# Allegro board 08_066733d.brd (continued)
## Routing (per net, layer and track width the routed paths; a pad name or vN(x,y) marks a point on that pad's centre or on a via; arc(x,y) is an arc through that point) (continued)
PD_01/OSPI0_SELB/PPI0_D06: length 48
  TOP w0.203: U1.R3 v1(26.62,49.34)
  L8_SIG w0.127: v1(4.57,24.38) 5.01,24.82 5.96,24.82 7.49,26.35 7.49,27.69 8.97,29.16 12.39,29.16 13.36,28.19 v2(17.91,28.19)
  BOTTOM w0.14: J3.63 3.31,24.38 v1(4.57,24.38) ; v1(26.62,49.34) 26.22,48.94 26.22,44.79 24.89,43.46 24.89,40.98 24.04,40.13 22.16,40.13 20.89,38.86 20.89,36.7 19.05,34.86 19.05,32.89 21.34,30.61 21.34,28.57 20.95,28.19 v2(17.91,28.19)
PD_02/UART1_RTSB/SH1_FLG10/ETH0_CRS: length 58.5
  TOP w0.203: v1(27.42,50.14) U1.P4
  L4_SIG w0.127: v1(27.42,50.14) 27.02,50.54 27.02,51.14 26.82,51.34 22.82,51.34 22.02,50.54 22.02,46.66 20.38,45.02 20.38,42.29 20,41.91 20,40.85 20.51,40.34 20.51,35.9 19.47,34.85 19.47,28.92 21.88,26.51 21.88,18.47 22.99,17.37 22.99,8.38 26.04,5.33 v1(26.54,5.33)
  BOTTOM w0.14: v1(26.54,5.33) 26.72,5.51 J2.36
PD_03/UART1_CTSB/SH0_FLG11/LP0_ACK/ETH0_PTPAUXIN2: length 50.2
  TOP w0.203: v1(26.62,48.54) U1.T3
  L4_SIG w0.127: v1(26.62,48.54) 26.22,48.14 24.82,48.14 24.22,47.54 24.22,45.05 23.75,44.58 23.75,40.07 24.32,39.5 24.32,38.54 23.16,37.39 23.16,34.59 22.61,34.04 22.61,18.86 23.88,17.59 23.88,10.79 26.29,8.38 26.29,7.3 27.56,6.03 v1(27.56,5.33)
  BOTTOM w0.14: v1(27.56,5.33) 27.35,5.54 J2.38
PD_04/UART1_RXB/OSPI0_DQS/PPI0_D07/TM0_ACI1: length 89.2
  TOP w0.203: U1.V2 v1(25.82,46.94)
  L4_SIG w0.127: 3.62,23.05 7.68,23.05 9.33,24.7 9.33,26.77 9.35,26.79 9.35,29.98 10.92,31.56 v2(11.75,31.56)
  L4_SIG w0.14: v1(1.4,24.13) 2.54,24.13 3.62,23.05
  L5_SIG w0.127: v1(25.82,46.94) 25.42,46.54 24.74,46.54 23.34,45.14 16.56,45.14 14.48,43.05 14.48,41.02 13.73,40.28 13.73,37.14 13.63,37.04 13.63,33 12.83,32.19 12.38,32.19 v2(11.75,31.56)
  L7_SIG w0.127: v1(1.4,24.13) 0.95,23.69 0.95,21.72 2.29,20.38 2.29,11.87 5.08,9.08 10.01,9.08 11.93,7.16 21.86,7.16 22.86,6.16 23.18,6.16 23.75,5.59 23.75,4.95 v1(24.26,4.44)
  BOTTOM w0.14: v1(1.4,24.13) 1.9,23.62 J3.65 ; J2.27 24.26,3.16 v1(24.26,4.44) 25.32,4.44 26.08,5.21 J2.34
PD_05/UART1_TXB/PPI0_D08/ETH0_PTPAUXIN1: length 81.4
  TOP w0.203: v1(25.02,46.14) U1.W1
  L7_SIG w0.127: v1(25.02,46.14) 23.98,47.18 17.59,47.18 17.08,46.67 13.84,46.67 6.35,39.18 6.35,38.61 5.6,37.86 4.01,37.86 3.02,36.87 3.02,24.87 v1(1.4,23.24) 3.05,21.59 3.05,12.13 5.4,9.78 10.41,9.78 11.3,8.89 24.89,8.89 v1(25.65,8.13)
  BOTTOM w0.14: J3.67 1.65,22.99 v1(1.4,23.24) ; J2.32 25.45,7.92 v1(25.65,8.13)
PD_06/UART0_CTSB/ETH0_RX_ER: length 50.4
  TOP w0.203: v1(26.62,47.74) U1.U3
  L4_SIG w0.127: v1(31.24,4.44) 31.75,4.95 31.75,5.46 31.05,6.16 29.27,6.16 28.19,7.24 28.19,13.57 26.02,15.74 26.02,17.66 26.34,17.98 26.34,28.18 25.21,29.31 25.21,32.51 25.39,32.69 25.39,34.68 25.21,34.86 25.21,38.48 25.46,38.73 25.46,40.69 25.22,40.93 25.22,44.15 26.22,45.14 26.22,47.34 v1(26.62,47.74)
  BOTTOM w0.14: v1(31.24,4.44) 31.24,3.16 J2.49
PD_07/UART0_RTSB/ETH0_COL: length 54.9
  TOP w0.203: v1(27.42,48.54) U1.T4
  L4_SIG w0.127: v1(30.48,4.44) 30.99,3.94 31.79,3.94 32.86,5.01 32.86,6.12 32.5,6.49 29.45,6.49 28.57,7.37 28.57,13.65 26.35,15.88 26.35,17.53 26.67,17.84 26.67,28.32 25.72,29.27 25.72,30.23 26.23,30.73 26.23,32.89 25.72,33.4 25.72,35.62 26.1,36 26.1,37.72 25.83,37.99 25.83,40.06 26.48,40.7 26.48,44.42 27.02,44.96 27.02,48.14 27.16,48.28 v1(27.42,48.54)
  BOTTOM w0.14: J2.47 30.48,3.13 v1(30.48,4.44)
PD_08/UART0_RXB/TM0_ACI0: length 57.5
  TOP w0.203: v1(28.22,49.34) U1.R5
  L4_SIG w0.127: v1(30.35,1.65) 31.93,3.23 32.01,3.23 32.03,3.24 33.85,3.24 34.78,4.17 34.78,4.52 34.29,5.01 34.29,7.18 35.2,8.09 35.2,12.3 33.38,14.13 33.38,15.77 33.57,15.97 33.57,17.55 29.54,21.58 29.54,27.8 30.35,28.62 30.35,30.39 30.8,30.83 30.8,34.48 29.46,35.81 29.46,38.61 28.58,39.49 28.58,43.52 28.62,43.56 28.62,48.94 v1(28.22,49.34)
  BOTTOM w0.14: J2.45 29.89,2.11 v1(30.35,1.65)
PD_09/UART0_TXB: length 63.4
  TOP w0.203: v1(29.02,50.14) U1.P5
  L4_SIG w0.127: v1(29.02,50.14) 29.42,49.74 29.42,44.94 30.1,44.26 30.1,42.16 31.08,41.19 31.08,40.53 31.56,40.05 31.56,38.39 32.19,37.76 32.19,36.24 33.2,35.23 33.2,32.94 32.96,32.7 31.25,32.7 31.13,32.58 31.13,30.69 30.68,30.25 30.68,28.48 29.87,27.67 29.87,23.07 34.26,18.68 34.26,16.09 36.51,13.84 36.51,8.76 34.67,6.92 34.67,5.14 35.17,4.64 35.17,3.99 34.04,2.86 33.15,2.86 32.38,2.1 32.38,1.46 32.08,1.16 30.09,1.16 v1(29.59,1.65)
  BOTTOM w0.14: J2.43 29.26,1.98 v1(29.59,1.65)
PD_10/UART2_RXB/PPI0_D09/TM0_ACI2: length 91.4
  TOP w0.203: v1(28.22,50.14) U1.R4
  L7_SIG w0.127: v1(28.57,5.33) 27.37,6.54 22.99,6.54 22.03,7.49 12.07,7.49 10.15,9.41 5.26,9.41 2.67,12 2.67,21.21 v1(1.4,22.48)
  L8_SIG w0.127: v1(28.22,50.14) 27.82,50.54 24.12,50.54 23.51,49.93 18.46,49.93 15.45,46.93 10.54,46.93 10.03,46.42 10.03,41.97 9.56,41.49 6.09,38.02 6.08,38.02 4.9,36.84 4.33,36.84 2.03,34.54 2.03,23.11 v1(1.4,22.48)
  BOTTOM w0.14: J3.69 1.52,22.35 v1(1.4,22.48) ; v1(28.57,5.33) 28.62,5.38 J2.42
PD_11/UART2_TXB/PPI0_D10: length 82.1
  TOP w0.203: v1(26.62,46.14) U1.W3
  L7_SIG w0.127: v1(26.62,46.14) 26.22,45.74 24.62,45.74 23.56,46.8 17.68,46.8 17.22,46.34 13.98,46.34 11.75,44.11 11.75,42.54 11.18,41.97 9.61,41.97 6.73,39.09 6.73,38.29 5.32,36.88 4.08,36.88 3.35,36.16 3.35,23.72 4.46,22.62 v1(4.57,22.48) 3.94,21.84 3.94,15.43 8.39,10.97 24.84,10.97 v1(27.69,8.13)
  BOTTOM w0.14: v1(27.69,8.13) 27.99,7.75 J2.40 ; J3.71 4.32,21.72 4.57,21.97 v1(4.57,22.48)
PD_12/ETH0_PHY_INT/TM0_TMR6/UART2_RTSB/PPI0_D11: length 109.9
  TOP w0.203: v1(27.42,46.14) U1.W4
  L4_SIG w0.127: v1(1.52,42.42) 2.41,41.53 2.41,27.24 0.97,25.79 0.97,22.02 1.78,21.21 v1(4.57,21.21)
  L7_SIG w0.127: v1(27.42,46.14) 27.02,45.74 27.02,45.14 26.73,44.84 24.5,44.84 23.43,45.91 14.22,45.91 12.13,43.82 12.13,42.35 10.41,40.64 8.76,40.64 7.11,38.99 7.11,36.92 3.68,33.49 3.68,24.07 5.02,22.73 5.02,21.65 v1(4.57,21.21) 6.92,18.86 6.92,13.53 8.51,11.94 13.02,11.94 13.91,12.83 21.34,12.83 22.48,11.68 25.78,11.68 v1(29.34,8.13)
  BOTTOM w0.14: v1(4.57,21.21) 4.45,21.08 J3.73 ; v1(29.34,8.13) 29.26,7.75 J2.44 ; v1(1.52,42.42) 1.9,42.04 J3.7
PD_13/TM0_TMR7/UART2_CTSB/PPI0_D12: length 84.7
  TOP w0.203: v1(29.82,45.34) U1.Y7
  L7_SIG w0.127: v1(30.35,8.13) 29.72,7.49 29.21,7.49 25.4,11.3 8.68,11.3 6.48,13.5 6.48,18.29 v1(4.57,20.19)
  L8_SIG w0.127: v1(4.57,20.19) 4.06,20.7 4.06,33.27 4.95,34.16 6.79,34.16 8.51,35.88 11.28,35.88 12.26,36.85 12.26,39.62 14.8,42.16 17.57,42.16 17.57,42.16 17.84,42.16 19.88,42.16 20.45,42.74 29.32,42.74 29.82,43.24 v1(29.82,45.34)
  BOTTOM w0.14: v1(30.35,8.13) 29.89,7.62 J2.46 ; v1(4.57,20.19) 4.32,20.45 J3.75
PD_14/TWI4_SCL/LP1_ACK/SH1_FLG9/PPI0_D13: length 50.3
  TOP w0.203: v1(29.02,46.14) U1.W6
  L8_SIG w0.127: v1(29.02,46.14) 28.63,45.75 24.35,45.75 24.2,45.9 13.33,45.9 10.65,43.23 10.65,40.62 9.78,39.75 9.78,38.93 9.02,38.16 7.94,38.16 5.59,35.81 4.25,35.81 2.54,34.1 2.54,21.59 v1(1.4,20.45)
  BOTTOM w0.14: J3.77 2.03,19.81 v1(1.4,20.45)
PD_15/TWI4_SDA/MSI0_D0/TM0_TMR15/PPI0_D14: length 90.8
  TOP w0.14: U20.8 v1(31.67,34.29)
  L4_SIG w0.127: v1(33.07,1.97) 33.07,1.38 32.51,0.83 11.3,0.83 3.61,8.52 3.61,18.81 2.86,19.56 v1(1.4,19.56)
  L7_SIG w0.127: v1(33.07,1.97) 32.51,2.52 32.51,4.76 33.15,5.4 33.15,6.35 32.57,6.93 32.57,9.6 26.09,16.07 26.09,17.2 27.3,18.41 27.3,29.99 26.8,30.5 26.8,32.32 27.43,32.96 27.43,33.39 27.69,33.65 28.77,33.65 28.78,33.65 29.15,33.65 30.04,34.54 31.42,34.54 v1(31.67,34.29)
  BOTTOM w0.14: J3.79 1.78,19.18 v1(1.4,19.56) ; J2.55 v1(33.07,1.97)
PD_15/TWI4_SDA/MSI0_D0/TM0_TMR15/PPI0_D14_Z: length 22.2
  TOP w0.14: v1(32.62,34.34) 32.32,34.64 32.32,35.24 32.62,35.55 U20.9 ; U12.9 26.72,35.51 27.18,35.05 v1(27.62,35.05)
  TOP w0.203: v1(29.02,45.34) U1.Y6
  L4_SIG w0.127: v1(29.02,45.34) 29.02,44.07 29.53,43.56 29.53,41.34 31.11,39.75 31.11,35.85 v1(32.62,34.34)
  L8_SIG w0.127: v1(32.62,34.34) 31.59,35.37 29.59,35.37 29.08,35.88 28.59,35.88 28.58,35.87 28.44,35.87 v1(27.62,35.05)
PE_00/TWI5_SCL/SPI3_SEL3B/PPI0_D15: length 51.7
  TOP w0.203: v1(29.82,46.14) U1.W7
  L8_SIG w0.127: v1(29.82,46.14) 29.42,45.74 29.42,45.28 29.41,45.26 29.41,45.18 28.67,44.44 24.25,44.44 23.48,45.21 16.82,45.21 13.46,41.85 13.46,41.49 11.86,39.89 11.86,38.28 11.21,37.63 9.6,37.63 6.52,34.54 4.57,34.54 3.56,33.53 3.56,20.95 v1(1.4,18.8)
  BOTTOM w0.14: J3.81 1.65,18.54 v1(1.4,18.8)
PE_01/TWI5_SDA/MSI0_D1/SPI3_SEL4B/PPI0_FS1/TM0_ACLK15: length 81.8
  TOP w0.14: U20.11 33.02,36.83 33.36,36.49 33.82,36.49 v1(33.82,36.48)
  L7_SIG w0.127: v1(33.82,36.48) 33.59,36.25 33.59,33.19 34.02,32.75 34.02,32.27 33.9,32.14 32.65,32.14 31.88,31.37 31.37,31.37 29.72,29.72 28.96,29.72 27.81,28.57 27.81,18.35 28.68,17.49 28.68,14.06 32.9,9.84 32.9,8.76 33.53,8.13 33.53,5.27 32.96,4.7 32.96,3.17 33.7,2.43 v1(33.7,1.71)
  L8_SIG w0.127: v1(5.46,29.59) 5.96,30.09 5.96,32.43 8.19,34.67 15.33,34.67 16.09,33.91 20.68,33.91 21.52,34.75 22.34,34.75 22.59,35 22.59,35.01 24.54,36.96 26.23,36.96 27.31,38.04 28.7,38.04 28.84,37.89 31.83,37.89 32.38,37.34 32.97,37.34 v1(33.82,36.48)
  BOTTOM w0.14: J3.45 4.32,29.97 4.45,30.1 4.95,30.1 v1(5.46,29.59) ; J2.57 v1(33.7,1.71)
PE_01/TWI5_SDA/MSI0_D1/SPI3_SEL4B/PPI0_FS1/TM0_ACLK15_Z: length 22.3
  TOP w0.14: U20.12 33.02,37.33 33.34,37.65 33.34,38.74 v1(33.46,38.86) ; U12.12 27.42,37.33 v1(27.69,37.59)
  TOP w0.203: v1(31.42,47.74) U1.U9
  L4_SIG w0.127: v1(33.46,38.86) 33.46,40.58 31.78,42.26 31.78,44.65 31.83,44.69 31.83,47.33 v1(31.42,47.74)
  L7_SIG w0.127: v1(33.46,38.86) 32.32,40.01 29.78,40.01 29.41,39.64 29.41,37.67 28.86,37.11 28.16,37.11 v1(27.69,37.59)
PE_02/TWI0_SCL/SPI1_SEL4B/HADC0_MUX0/PPI0_FS2: length 40.5
  TOP w0.203: v1(30.62,46.94) U1.V8
  L7_SIG w0.127: v1(4.57,29.59) 4.57,32.04 5,32.48 5,33.45 10.48,38.93 11.87,38.93 13.84,40.89 13.84,42.1 16.89,45.15 23.26,45.15 24.22,44.18 28.69,44.18 29.43,44.94 29.43,47.26 29.53,47.35 30.21,47.35 v1(30.62,46.94)
  BOTTOM w0.14: J3.47 4.32,29.34 v1(4.57,29.59)
PE_03/TWI0_SDA/SPI2_SEL3B/HADC0_MUX2/PPI0_FS3/TM0_ACLK4: length 40.3
  TOP w0.203: v1(30.62,46.14) U1.W8
  L7_SIG w0.127: v1(4.57,28.83) 5.02,29.27 5.02,30.77 5.28,31.04 5.83,31.04 6.67,31.88 6.67,33.78 10.51,37.63 13.3,37.63 14.86,39.18 14.86,41.24 18.14,44.51 19.18,44.51 20.78,42.91 21.51,42.91 22.45,43.85 29.18,43.85 30.21,44.88 30.21,45.73 v1(30.62,46.14)
  BOTTOM w0.14: J3.49 4.45,28.7 v1(4.57,28.83)
PE_04/TWI2_SCL/HADC0_MUX1/PPI0_CLK: length 38.8
  TOP w0.203: v1(31.42,46.14) U1.W9
  L7_SIG w0.127: v1(31.42,46.14) 31.02,45.74 31.02,44.61 29.13,42.72 22.32,42.72 21.55,41.96 19.92,41.96 18.67,40.7 18.67,35.75 15.49,32.58 8.12,32.58 6.15,30.61 v1(5.46,30.61)
  BOTTOM w0.14: J3.43 5.46,30.61 v1(5.46,30.61)
PE_05/TWI2_SDA/PPI0_D00: length 48.7
  TOP w0.203: v1(32.22,46.94) U1.V10
  L7_SIG w0.127: v1(32.22,46.94) 31.83,47.33 31.83,47.9 31.6,48.13 28.77,48.13 28.63,48 28.63,45.2 27.94,44.51 24.36,44.51 23.35,45.53 16.76,45.53 13.4,42.16 13.4,41.08 12.51,40.2 10.35,40.2 8.64,38.48 8.13,38.48 7.44,37.8 7.44,36.78 4.01,33.35 4.01,28.37 4.19,28.19 4.83,28.19 v1(5.46,27.56)
  BOTTOM w0.14: J3.51 4.45,28.07 4.95,28.07 v1(5.46,27.56)
PE_06/TM0_TMR8/SH0_FLG2/MSI0_D2/PPI0_D01: length 67.7
  TOP w0.14: U22.3 28.64,32.07 v1(28.45,32.26)
  L4_SIG w0.127: v1(28.45,32.26) 28.7,32.01 28.7,30.86 28.19,30.35 27.51,30.35 27.3,30.15 27.3,29.34 28.17,28.47 28.17,19.08 29.78,17.46 29.78,15.94 29.4,15.56 29.4,9.4 29.84,8.95 29.84,7.68 30.38,7.15 33.43,7.15 33.96,6.62 33.96,4.87 34.34,4.5 v1(34.34,4.34)
  L8_SIG w0.127: v1(4.57,27.56) 5.21,28.19 5.78,28.19 6.29,28.7 6.29,32.3 8.33,34.34 15.19,34.34 16.07,33.46 19.99,33.46 21.2,32.26 23.05,32.26 23.63,32.83 27.84,32.83 27.89,32.78 27.92,32.78 v1(28.45,32.26)
  BOTTOM w0.14: J2.59 v1(34.34,4.34) ; J3.53 3.31,27.56 v1(4.57,27.56)
PE_06/TM0_TMR8/SH0_FLG2/MSI0_D2/PPI0_D01_Z: length 38.1
  TOP w0.14: U22.2 29.1,32.57 28.96,32.71 v1(28.96,33.22) ; v1(21.95,33.45) 22.62,33.45 23.32,32.75 U21.2
  TOP w0.203: v1(32.22,47.74) U1.U10
  L7_SIG w0.127: v1(21.95,33.45) 20.71,33.45 19.44,34.72 19.44,38.37 21.86,40.79 21.86,41.26 22.66,42.06 31.69,42.06 32.65,43.03 32.65,47.31 v1(32.22,47.74)
  L8_SIG w0.127: v1(21.95,33.45) 22.13,33.27 25.02,33.27 25.91,34.16 26.77,34.16 27.28,33.66 28.52,33.66 v1(28.96,33.22)
PE_07/TM0_TMR9/SH0_FLG3/SPI1_RDY/PPI0_D02: length 53.6
  TOP w0.203: v1(34.62,46.14) U1.W12
  L7_SIG w0.127: v1(4.57,26.54) 4.14,26.11 4.14,25.15 4.39,24.89 5.71,24.89 6.54,24.07 8.74,24.07 9.31,24.64 21.82,24.64 25.67,28.49 25.67,29.69 24.82,30.54 24.82,32.97 26.16,34.31 27.85,34.31 28.47,34.92 28.86,34.92 29.3,35.37 31.88,35.37 33.42,36.92 34.25,36.92 34.59,37.26 34.59,38.58 33.97,39.2 33.97,40.26 34.86,41.15 34.86,44.51 35.03,44.68 35.03,45.73 v1(34.62,46.14)
  BOTTOM w0.14: v1(4.57,26.54) 4.32,26.8 J3.55
PE_08/TM0_TMR0/MSI0_D3/PPI0_D03: length 68.3
  TOP w0.14: U22.6 v1(29.22,29.29)
  L7_SIG w0.127: v1(29.22,29.29) 28.38,28.45 28.38,18.54 29.84,17.08 29.84,13.36 33.23,9.97 33.23,8.89 33.86,8.26 33.86,3.15 v1(34.97,2.03)
  L8_SIG w0.127: v1(5.14,25.91) 5.97,25.91 6.68,26.62 6.68,32.08 7.37,32.77 11.43,32.77 11.57,32.63 17.67,32.63 19.11,31.18 20.88,31.18 21.34,30.72 21.34,29.34 22.8,27.88 27.82,27.88 v1(29.22,29.29)
  BOTTOM w0.14: J2.61 v1(34.97,2.03) ; v1(5.14,25.91) 5.08,25.97 4.51,25.97 4.32,26.16 J3.57
PE_08/TM0_TMR0/MSI0_D3/PPI0_D03_Z: length 41.8
  TOP w0.14: U21.5 22.35,31.07 v1(22.1,30.81) ; U22.5 28.84,31.07 28.77,30.99 28.76,30.99 28.51,30.74 v1(28.51,29.92)
  TOP w0.203: v1(31.42,46.94) U1.V9
  L7_SIG w0.127: v1(31.42,46.94) 31.81,46.55 31.81,43.56 30.65,42.39 22.45,42.39 21.69,41.63 20.1,41.63 19.05,40.58 19.05,32.89 21.13,30.81 v1(22.1,30.81)
  L8_SIG w0.127: v1(22.1,30.81) 21.72,30.44 21.72,29.71 22.16,29.28 23.23,29.28 23.24,29.27 23.24,29.27 24,30.03 26.93,30.03 27.68,29.28 27.86,29.28 v1(28.51,29.92)
PE_09/TM0_TMR1/MSI0_CLK/PPI0_D04/ETH0_PTPAUXIN3: length 93.1
  TOP w0.14: v1(37.41,28.99) 37.58,29.16 U25.8
  L5_SIG w0.127: v1(37.41,28.99) 37.45,28.96 37.45,18.3 38.54,17.21 38.54,8 40.26,6.29 44.96,6.29 45.72,5.52 45.72,4.64 44.64,3.56 35.62,3.56 34.77,4.41 34.77,6.24 v1(33.07,7.94)
  L8_SIG w0.127: v1(37.41,28.99) 36.47,28.99 35.16,27.69 28.64,27.69 28.07,27.11 21.46,27.11 19.34,29.24 19.34,29.94 18.1,31.18 16.64,31.18 16.19,30.73 11.81,30.73 10.16,32.38 7.49,32.38 7.01,31.9 7.01,26.38 5.78,25.15 4.95,25.15 v1(4.57,25.53)
  BOTTOM w0.14: J2.56 v1(33.07,7.94) ; v1(4.57,25.53) 3.18,25.53 J3.59
PE_09/TM0_TMR1/MSI0_CLK/PPI0_D04/ETH0_PTPAUXIN3_Z: length 24.5
  TOP w0.14: U23.9 38.72,35.83 v1(39.43,35.12) ; U25.9 v1(38.53,29.73)
  TOP w0.203: v1(32.22,46.14) U1.W10
  L4_SIG w0.127: v1(39.43,35.12) 38.93,35.12 38.54,35.5 35.94,35.5 35.43,36 35.43,37.38 33.97,38.84 33.97,40.32 34.29,40.64 34.29,41.47 32.69,43.07 32.69,45.67 v1(32.22,46.14)
  BOTTOM w0.14: v1(38.53,29.73) 38.53,33.77 39.43,34.67 v1(39.43,35.12)
PE_10/TM0_TMR2/SPI0_SEL4B/PPI0_D05: length 77
  TOP w0.14: v1(42.02,44.14) 40.52,44.14 39.92,44.74 22.99,44.74 22.45,45.28 18.92,45.28 17.06,43.41 14.64,43.41 14.29,43.05 14.29,40.2 14.83,39.66 14.83,39.21 14.51,38.89 14.51,38.89 12.19,36.58 12.19,35.37 10.79,33.97 10.79,31.18 11.53,30.45 11.53,30.45 11.65,30.32 11.65,26.11 11.44,25.9 9.9,25.9 9.27,25.27 9.27,24.89 7.38,23 3.56,23 v1(1.42,25.14)
  TOP w0.203: v1(41.02,57.34) U1.F20
  BOTTOM w0.14: v1(41.02,57.34) 41.42,56.94 41.42,45.74 42.02,45.14 v1(42.02,44.14) ; v1(1.42,25.14) 1.67,24.89 J3.61
PE_11/ETH1_REFCLK/SH1_FLG7: length 79
  TOP w0.203: v1(40.22,56.54) U1.G19
  L8_SIG w0.127: v1(4.57,19.3) 5.78,19.3 7.68,21.21 17.72,21.21 20.05,18.87 26.05,18.87 27.75,20.57 35.7,20.57 35.83,20.7 35.83,25.66 36.19,26.02 36.84,26.02 37.65,26.02 38.61,26.98 38.61,27.56 38.96,27.9 41.88,27.9 v1(42.1,27.69)
  BOTTOM w0.14: v1(4.57,19.3) 5.08,19.81 J3.78 ; v1(40.22,56.54) 40.46,56.3 40.62,56.14 40.62,44.98 41.44,44.16 41.44,28.35 v1(42.1,27.69)
PE_12/ETH1_TXEN/SH0_FLG8: length 46.1
  TOP w0.203: v1(39.42,55.74) U1.H18
  L7_SIG w0.127: v1(39.42,55.74) U1.H18 24.32,55.34 23.62,54.64 21.59,54.64 21.56,54.61 20.24,54.61 17.77,52.18 9.94,52.18 8.16,50.41 8.16,43.98 v1(5.33,41.15)
  BOTTOM w0.14: v1(5.33,41.15) 5.71,40.77 J3.12
PE_13/ETH1_TXD0/SH1_FLG13: length 45.2
  TOP w0.203: v1(38.62,54.94) U1.J17
  L7_SIG w0.127: v1(5.33,40.39) 8.51,43.56 8.51,50.04 10.27,51.8 18.37,51.8 20.13,53.54 23.42,53.54 24.42,54.54 U1.J17 v1(38.62,54.94)
  BOTTOM w0.14: J3.14 5.59,40.13 v1(5.33,40.39)
PE_14/ETH1_TXD1/SPI2_SEL7B: length 46.6
  TOP w0.203: v1(37.82,53.34) U1.K16
  L7_SIG w0.127: v1(4.57,39.12) 4.57,39.5 4.7,39.62 5.27,39.62 9.59,43.94 9.59,50.48 10.53,51.42 18.91,51.42 20.03,52.54 23.42,52.54 24.62,53.74 U1.K16 v1(37.82,53.34)
  BOTTOM w0.14: J3.16 6.65,39.62 5.08,39.62 v1(4.57,39.12)
PE_15/ETH1_RXD0/SPI0_SEL6B: length 45.2
  TOP w0.203: v1(39.42,56.54) U1.G18
  L7_SIG w0.127: v1(39.42,56.54) U1.G18 22.62,56.14 21.42,54.94 19.52,54.94 17.05,52.51 9.09,52.51 v1(8.82,52.24)
  BOTTOM w0.14: v1(8.82,52.24) 8.82,46.41 8,45.59 8,41.66 7.75,41.4 J3.10
PF_00/ETH1_RXD1/SPI3_RDY/SPI0_SEL7B: length 47.8
  TOP w0.203: v1(40.22,57.34) U1.F19
  L7_SIG w0.127: v1(40.22,57.34) U1.F19 25.42,56.94 25.34,57.02 21.91,57.02 20.92,56.04 19.82,56.04 16.71,52.93 8.59,52.93 7.75,52.09 7.75,44.45 v1(5.33,42.04)
  BOTTOM w0.14: J3.8 6.78,42.04 v1(5.33,42.04)
PF_01/ETH1_MDIO/SH0_FLG7: length 46.7
  TOP w0.203: v1(39.42,57.34) U1.F18
  L7_SIG w0.127: v1(5.33,43.31) 6.03,43.31 7.37,44.64 7.37,52.2 8.47,53.3 14.82,53.3 16.07,54.55 17.63,54.55 20.55,57.47 25.45,57.47 25.72,57.74 39.02,57.74 v1(39.42,57.34)
  BOTTOM w0.14: v1(5.33,43.31) 6.78,43.31 J3.4
PF_02/ETH1_MDC/SH0_FLG6: length 52.3
  TOP w0.203: v1(41.02,58.14) U1.E20
  L7_SIG w0.127: v1(41.02,58.14) 40.62,58.54 25.84,58.54 25.39,58.99 18.77,58.99 17.12,57.34 17.12,55.84 16.62,55.34 7.84,55.34 6.22,53.72 6.22,48.39 4.57,46.74 v1(4.57,43.31)
  BOTTOM w0.14: J3.6 5.21,42.67 v1(4.57,43.31)
PF_03/ETH1_CRS/SH0_FLG10/USB0_STP: length 89.1
  TOP w0.203: v1(40.22,58.14) U1.E19
  L4_SIG w0.127: v1(58.8,35.56) 55.37,38.99 55.37,41.91 54.18,43.1 54.18,52.14 54.1,52.22 54.1,52.26 48.62,57.74 40.62,57.74 v1(40.22,58.14)
  L7_SIG w0.127: v1(40.22,58.14) 40.62,57.74 40.62,53.84 39.72,52.94 24.62,52.94 23.82,52.14 22.02,52.14 20.82,51.04 10.78,51.04 10.03,50.29 10.03,43.81 v1(5.33,39.12)
  BOTTOM w0.14: v1(5.33,39.12) 5.59,38.86 J3.18 ; J1.76 58.04,36.32 v1(58.8,35.56)
PF_04/USB0_D7/TM0_ACLK13: length 34.8
  TOP w0.203: v1(38.62,55.74) U1.H17
  L5_SIG w0.127: v1(54.23,35.43) 52.32,37.34 52.32,44.74 50.93,46.13 50.93,51.37 46.74,55.56 42.8,55.56 42.58,55.34 39.02,55.34 v1(38.62,55.74)
  BOTTOM w0.14: J1.72 54.61,35.05 v1(54.23,35.43)
PF_05/MLB0_CLKOUT/USB0_D6/TM0_CLK: length 36.3
  TOP w0.203: v1(37.02,54.94) U1.J16
  L5_SIG w0.127: v1(54.23,34.67) 51.99,36.91 51.99,44.53 50.55,45.97 50.55,51.28 47.29,54.54 U1.J16 v1(37.02,54.94)
  BOTTOM w0.14: v1(54.23,34.67) 54.48,34.42 J1.70
PF_06/SH1_FLG2/SPI1_SEL7B/USB0_D5: length 38.1
  TOP w0.203: v1(38.62,56.54) U1.G17
  L5_SIG w0.127: v1(55.25,33.91) 55.75,34.42 55.75,42.16 54.36,43.56 54.36,50.61 49.33,55.64 47.72,55.64 46.36,57 42.33,57 42.27,56.94 39.02,56.94 v1(38.62,56.54)
  BOTTOM w0.14: J1.68 55.37,33.78 v1(55.25,33.91)
PF_07/SH1_FLG3/SPI3_SEL2B/USB0_D4: length 40.7
  TOP w0.203: v1(41.02,58.94) U1.D20
  L5_SIG w0.127: v1(58.8,34.29) 58.17,34.92 57.53,34.92 57.09,35.37 57.09,43.05 56.13,44.01 56.13,51.75 49.34,58.55 47.31,58.55 46.61,59.25 45.15,59.25 44.96,59.44 43.12,59.44 42.62,58.94 v1(41.02,58.94)
  BOTTOM w0.14: J1.66 57.91,33.15 58.17,33.4 58.17,33.65 v1(58.8,34.29)
PF_08/SPI3_SEL6B/SH1_FLG8/USB0_NXT/TM0_TMR11: length 40.8
  TOP w0.203: v1(40.22,58.94) U1.D19
  L5_SIG w0.127: v1(58.04,35.56) 57.53,36.07 57.53,43.31 56.52,44.32 56.52,54.42 52.26,58.67 50.48,58.67 48.83,60.33 42.54,60.33 41.55,59.33 40.61,59.33 v1(40.22,58.94)
  BOTTOM w0.14: J1.74 57.91,35.69 v1(58.04,35.56)
PF_09/SH0_FLG9/USB0_DIR: length 36.8
  TOP w0.203: v1(41.02,59.74) U1.C20
  L4_SIG w0.127: v1(58.42,37.08) 55.75,39.75 55.75,52.77 49.58,58.94 44.82,58.94 44.02,59.74 v1(41.02,59.74)
  BOTTOM w0.14: v1(58.42,37.08) 56.81,37.08 J1.78
PF_10/SH1_FLG4/USB0_D3: length 41.8
  TOP w0.203: v1(39.42,58.14) U1.E18
  L5_SIG w0.127: v1(39.42,58.14) 39.82,58.54 41.52,58.54 42.4,57.66 48.7,57.66 55.75,50.61 55.75,43.75 56.64,42.86 56.64,34.73 58.1,33.27 v1(58.8,33.27)
  BOTTOM w0.14: v1(58.8,33.27) 58.04,32.51 J1.64
PF_11/SH1_FLG5/USB0_D2: length 41
  TOP w0.203: v1(38.62,57.34) U1.F17
  L5_SIG w0.127: v1(55.25,32.26) 56.2,33.21 56.2,42.74 55.37,43.56 55.37,50.36 49.69,56.04 48.02,56.04 46.73,57.33 42.26,57.33 41.85,57.74 39.02,57.74 v1(38.62,57.34)
  BOTTOM w0.14: v1(55.25,32.26) 55.63,31.88 J1.62
PF_12/SH0_FLG13/USB0_D1: length 40.9
  TOP w0.203: v1(37.82,55.74) U1.H16
  L5_SIG w0.127: v1(55.25,31.5) 54.76,31.98 54.76,35.88 53.53,37.11 53.53,38.91 54.36,39.74 54.36,42.87 53.72,43.51 53.72,50.67 49.91,54.48 48.32,54.48 46.88,55.93 41.68,55.93 41.47,56.14 38.22,56.14 v1(37.82,55.74)
  BOTTOM w0.14: J1.60 55.5,31.24 v1(55.25,31.5)
PF_13/SH0_FLG12/USB0_D0: length 46.8
  TOP w0.203: v1(41.02,60.54) U1.B20
  L4_SIG w0.127: v1(58.04,31.5) 59.44,32.89 59.44,40.39 59.06,40.77 58.04,40.77 56.52,42.29 56.52,55.75 51.73,60.54 v1(41.02,60.54)
  BOTTOM w0.14: v1(58.04,31.5) 58.04,30.86 57.79,30.61 J1.58
PF_14/SH1_FLG12/USB0_CLK: length 38.8
  TOP w0.203: v1(40.22,59.74) U1.C19
  L4_SIG w0.127: v1(40.22,59.74) 40.62,60.14 49.4,60.14 50.93,58.61 52.7,58.61 56.13,55.17 56.13,40.13 v1(58.42,37.85)
  BOTTOM w0.14: J1.80 58.17,37.59 v1(58.42,37.85)
PF_15/CAN0_RX/TM0_ACI4: length 53.3
  TOP w0.203: v1(32.22,48.54) U1.T10
  L4_SIG w0.127: v1(36.32,5.33) 38.58,7.59 38.58,18.42 35.69,21.32 35.69,28.07 40.21,32.59 40.21,36.6 37.21,39.6 37.21,40.58 34.23,43.56 34.23,47.88 33.96,48.15 32.61,48.15 v1(32.22,48.54)
  BOTTOM w0.14: v1(36.32,5.33) 36.32,6.61 J2.66
PG1: length 34.9
  TOP w0.254: v2(21.08,12.06) 21.27,12.26 R100.1 20.06,12.77 19.87,12.96 19.87,13.26 19.86,13.26 19.86,13.76 19.63,13.99 VR1.1 ; U17.2 46.46,14.67 46.73,14.4 46.81,14.4 v2(47.12,14.1)
  L8_SIG w0.305: v2(21.08,12.06) 28.7,12.06 29.91,13.27 32.39,13.27 34.99,10.67 42.8,10.67 43.94,11.81 46.36,11.81 47.12,12.57 v2(47.12,14.1)
PG2: length 12.9
  TOP w0.254: v2(43.56,13.46) 44.58,13.46 44.84,13.72 U17.11
  TOP w0.305: v2(43.56,13.46) 43.18,13.08 R104.1
  L8_SIG w0.305: v2(43.56,13.46) 42.43,14.6 v2(34.92,14.6)
  BOTTOM w0.254: R92.1 v2(34.92,14.6)
PG_00/CAN0_TX/TM0_ACLK10: length 48.5
  TOP w0.203: v1(33.82,47.74) U1.U11
  L5_SIG w0.127: v1(39.37,8.13) 38.87,8.62 38.87,20.62 38.04,21.46 38.04,29.72 35.43,32.32 35.14,32.32 34.7,32.76 34.7,33.5 33.53,34.67 33.53,36.17 33.39,36.31 33.39,36.66 33.39,37.96 33.97,38.54 33.97,38.99 33.38,39.58 33.38,47.3 v1(33.82,47.74)
  BOTTOM w0.14: v1(39.37,8.13) 35.99,8.13 35.61,7.75 J2.64
PG_01/CAN1_RX/SPI2_SEL6B/MSI0_CMD/TM0_ACI11: length 45.3
  TOP w0.14: v1(28.32,37.59) 28.59,37.33 U20.3
  L4_SIG w0.127: v1(33.7,9.35) 33.7,11.95 33.05,12.61 33.05,15.91 33.24,16.11 33.24,17.41 29.21,21.45 29.21,27.94 30.02,28.75 30.02,30.3 29.79,30.53 29.79,32.72 30.47,33.39 30.47,34.24 29.13,35.57 29.13,36.78 v1(28.32,37.59)
  L5_SIG w0.127: v1(33.7,9.35) 37.66,5.39 37.66,4.76 37.97,4.44 v1(38.61,4.44)
  BOTTOM w0.14: J2.72 38.15,4.91 v1(38.61,4.44) ; J2.58 v1(33.7,9.35)
PG_01/CAN1_RX/SPI2_SEL6B/MSI0_CMD/TM0_ACI11_Z: length 21.9
  TOP w0.14: U20.2 29.1,37.83 28.96,37.97 v1(28.96,38.48) ; U12.2 23.19,37.83 v1(22.29,38.73)
  TOP w0.203: v1(33.82,46.14) U1.W11
  L7_SIG w0.127: v1(33.82,46.14) 34.21,45.75 34.21,44.91 34.48,44.64 34.48,42.44 32.43,40.39 29.53,40.39 28.96,39.81 v1(28.96,38.48) 28.52,38.04 22.98,38.04 v1(22.29,38.73)
PG_02/CAN1_TX/SPI0_SEL5B/MSI0_D4: length 37.3
  TOP w0.14: U22.8 v1(31.67,29.03)
  L4_SIG w0.127: v1(35.61,1.71) 35.61,2.97 v1(37.08,4.44)
  L7_SIG w0.127: v1(31.67,29.03) 31.35,28.7 31.24,28.7 29.59,27.05 29.59,20.89 33.27,17.21 33.27,15.13 33.05,14.9 33.05,13.75 33.82,12.98 33.82,10.82 37.64,7 37.64,5 v1(37.08,4.44)
  BOTTOM w0.14: J2.70 37.59,6.61 37.59,4.95 v1(37.08,4.44) ; J2.63 v1(35.61,1.71)
PG_02/CAN1_TX/SPI0_SEL5B/MSI0_D4_Z: length 34.3
  TOP w0.14: v1(32.62,29.46) U22.9 ; U21.9 27.04,30.57 v1(27.75,29.86)
  TOP w0.203: v1(33.82,46.94) U1.V11
  L4_SIG w0.127: v1(33.82,46.94) 33.39,46.51 33.39,42.94 35.81,40.51 36.45,40.51 36.77,40.2 36.77,39.12 38.23,37.66 38.23,36.64 39.29,35.57 39.67,35.57 39.88,35.37 39.88,34.8 38.35,33.27 38.35,32.45 35.05,29.15 32.94,29.15 v1(32.62,29.46)
  L8_SIG w0.127: v1(27.75,29.86) 28.25,30.35 31.74,30.35 v1(32.62,29.46)
PG_03/UART3_TXB: length 67
  TOP w0.203: v1(36.22,45.34) U1.Y14
  L4_SIG w0.127: v1(36.22,45.34) 36.22,44.87 38.1,42.99 38.1,42.12 39.51,40.71 39.51,39.8 41.2,38.11 41.2,30.53 37.02,26.35 37.02,25.59 v1(37.02,25.59)
  L8_SIG w0.127: v1(37.02,25.59) 37.47,25.15 37.47,21.08 36.58,20.19 31.18,20.19 29.53,18.54 19.92,18.54 17.63,20.83 8,20.83 5.84,18.67 v1(4.57,18.67)
  BOTTOM w0.14: v1(4.57,18.67) 5.08,19.18 J3.80
PG_04/UART3_RXB/TM0_ACI13: length 72.8
  TOP w0.203: v1(35.42,46.94) U1.V13
  L4_SIG w0.127: v1(39.59,20.57) 36.17,23.99 36.17,26.52 40.54,30.89 40.54,36.74 38.99,38.29 38.99,39.18 38.3,39.87 38.3,40.12 35.02,43.4 35.02,46.54 v1(35.42,46.94)
  L8_SIG w0.127: v1(4.57,18.03) 6.48,18.03 8.13,19.68 9.48,19.68 11.01,18.16 29.65,18.16 30.42,18.92 36.07,18.92 38.23,21.08 39.08,21.08 v1(39.59,20.57)
  BOTTOM w0.14: v1(4.57,18.03) 5.08,18.54 J3.82
PG_05/SPI3_CLK/TM0_ACLK11: length 38
  TOP w0.203: v1(36.22,46.14) U1.W14
  L7_SIG w0.127: v1(61.09,45.72) 61.09,37.34 v1(61.72,36.7)
  L8_SIG w0.127: v1(61.09,45.72) 59.56,45.72 58.93,46.36 54.58,46.36 53.11,44.89 41.06,44.89 41,44.83 38.43,44.83 38.22,45.04 38.22,45.54 38.02,45.74 36.62,45.74 v1(36.22,46.14)
  BOTTOM w0.14: J1.77 61.47,36.96 v1(61.72,36.7)
PG_06/SPI3_MISO: length 41.4
  TOP w0.203: v1(33.82,48.54) U1.T11
  L5_SIG w0.127: v1(61.72,37.46) 60.58,38.61 60.58,48.89 v1(59.94,49.53)
  L8_SIG w0.127: v1(59.94,49.53) 48.64,49.53 48.04,48.93 34.21,48.93 v1(33.82,48.54)
  BOTTOM w0.14: v1(61.72,37.46) 61.59,37.59 J1.79
PG_07/SPI3_MOSI/TM0_ACLK12: length 39.3
  TOP w0.203: v1(34.62,47.74) U1.U12
  L5_SIG w0.127: v1(58.42,38.61) 59.44,39.62 59.44,48.01 v1(59.94,48.51)
  L8_SIG w0.127: v1(34.62,47.74) 35.01,48.13 48.42,48.13 48.48,48.07 49.59,48.07 50.67,49.15 59.31,49.15 v1(59.94,48.51)
  BOTTOM w0.14: J1.81 58.8,38.23 v1(58.42,38.61)
PG_08/SPI3_SEL1B/MSI0_D5/SPI3_SSB: length 96.8
  TOP w0.14: U22.11 v1(33.59,31.57)
  L7_SIG w0.127: v1(33.59,31.57) 33.09,31.57 28.83,27.3 28.83,18.8 30.35,17.27 30.35,16.17 31.18,15.34 31.18,12.49 34.79,8.88 34.79,3.49 v1(36.24,2.03) 36.24,1.29 36.45,1.08 52.13,1.08 55.05,4 55.05,9.12 56.41,10.48 56.41,15.75 57.23,16.56 57.23,38.3 v1(58.42,39.5)
  BOTTOM w0.14: J2.65 v1(36.24,2.03) ; J1.83 59.05,38.86 v1(58.42,39.5)
PG_08/SPI3_SEL1B/MSI0_D5/SPI3_SSB_Z: length 31.8
  TOP w0.14: v1(27.67,32.39) 27.67,32.39 27.67,32.39 27.36,32.07 U21.12 ; v1(33.59,32.58) 33.08,32.07 U22.12
  TOP w0.203: v1(37.02,45.34) U1.Y15
  L7_SIG w0.127: v1(27.67,32.39) 27.13,31.85 27.13,30.63 27.41,30.35 28.89,30.35 30.29,31.75 31.72,31.75 32.54,32.58 v1(33.59,32.58) ; v1(37.02,45.34) 37.02,44.82 38.29,43.55 38.29,42.04 39.18,41.15 39.18,39.27 38.54,38.63 38.54,35.28 39.37,34.46 v1(39.37,33.55)
  L8_SIG w0.127: v1(33.59,32.58) 33.65,32.52 35.25,32.52 36.08,33.35 39.17,33.35 v1(39.37,33.55)
PG_09/UART3_RTSB/SPI1_SEL6B/SH0_FLG14/MSI0_D6/TM0_ACLK1: length 87.8
  TOP w0.14: U25.3 34.74,32.07 34.23,32.58 v1(34.23,33.34)
  L7_SIG w0.127: v1(36.88,1.71) 36.88,2.49 35.12,4.25 35.12,9.02 33.45,10.69 33.45,12.2 32,13.65 32,14.99 31.08,15.91 31.08,18.9 29.21,20.76 29.21,27.18 33.07,31.04 33.77,31.04 34.54,31.81 34.54,33.02 v1(34.23,33.34)
  L8_SIG w0.127: v1(36.88,1.71) 36.26,1.09 12.37,1.09 9.33,4.13 9.33,7.43 7.89,8.88 7.89,16.65 v1(9.4,18.16)
  BOTTOM w0.14: J3.84 9.14,17.91 v1(9.4,18.16) ; J2.67 v1(36.88,1.71)
PG_09/UART3_RTSB/SPI1_SEL6B/SH0_FLG14/MSI0_D6/TM0_ACLK1_Z: length 18.2
  TOP w0.14: v1(34.54,39.24) 34.54,38.87 35.13,38.28 U23.2 ; U25.2 v1(35.13,33.07)
  TOP w0.203: v1(34.62,46.94) U1.V12
  L5_SIG w0.127: v1(35.13,33.07) 35.13,34.72 34.67,35.18 34.04,35.18 33.86,35.36 33.86,35.89 34.73,36.77 34.73,38.29 34.54,38.48 v1(34.54,39.24) 34.54,43.43 34.22,43.76 34.22,46.54 v1(34.62,46.94)
PG_10/UART3_CTSB/MSI0_D7/SH1_FLG14/TM0_ACLK3: length 84.1
  TOP w0.14: U25.6 v1(35.13,30.1)
  L7_SIG w0.127: v1(35.13,30.1) 35.13,24.02 32.87,21.76 32.87,18.14 33.6,17.4 33.6,14.99 33.38,14.76 33.38,14.05 35.2,12.22 35.2,11.09 36.68,9.61 36.68,8.6 37.97,7.3 37.97,2.49 v1(37.51,2.03)
  L8_SIG w0.127: v1(9.4,17.53) 9.84,17.96 9.84,18.34 9.58,18.6 9.14,18.6 7.56,17.02 7.56,8.64 9,7.19 9,3.99 12.23,0.76 36.83,0.76 37.51,1.44 v1(37.51,2.03)
  BOTTOM w0.14: v1(9.4,17.53) 9.14,17.27 J3.86 ; J2.69 v1(37.51,2.03)
PG_10/UART3_CTSB/MSI0_D7/SH1_FLG14/TM0_ACLK3_Z: length 24
  TOP w0.14: U23.5 34.43,36.33 34.29,36.19 v1(34.29,35.62) ; v1(34.35,30.92) 34.5,31.07 U25.5
  TOP w0.203: v1(34.62,48.54) U1.T12
  L4_SIG w0.127: v1(34.35,30.92) 35.75,32.32 35.75,33.46 35.43,33.78 35.43,35.37 35.18,35.62 v1(34.29,35.62)
  L5_SIG w0.127: v1(34.29,35.62) 35.76,37.1 35.76,38.3 36.7,39.24 36.7,40.26 35.01,41.95 35.01,48.15 v1(34.62,48.54)
PG_11/SH1_FLG15: length 53.4
  TOP w0.203: v1(26.62,60.54) U1.B3
  L7_SIG w0.127: v1(54.23,37.34) 54.67,37.78 54.86,37.78 55.5,38.42 55.5,42.16 54.17,43.5 54.17,53.72 50.8,57.09 50.8,58.17 48.38,60.58 44.83,60.58 43.56,61.84 27.32,61.84 27.02,61.54 27.02,60.94 v1(26.62,60.54)
  BOTTOM w0.14: v1(54.23,37.34) 54.61,37.34 55.5,38.23 J1.82
PG_12/TM0_TMR3/SPI2_SEL4B/SH1_FLG11/OSPI0_SEL3B: length 123.1
  TOP w0.203: v1(25.82,61.34) U1.A2
  L5_SIG w0.127: v1(1.52,45.34) 2.02,45.84 2.02,55.76 3.52,57.26 3.52,58.44 4.22,59.14 12.22,59.14 13.41,60.32 14.42,61.34 19.54,61.34 19.94,60.94 25.42,60.94 v1(25.82,61.34)
  L8_SIG w0.127: v1(32.43,5.4) 31.66,6.17 19.76,6.17 19.11,5.52 19.11,3.24 18.73,2.86 14.1,2.86 12.76,4.19 12.76,8.38 8.95,12.19 8.95,16.68 9.37,17.09 9.66,17.09 10.35,17.78 10.35,18.35 9.77,18.93 8.32,18.93 6.79,17.4 6.79,14.92 6.22,14.35 2.03,14.35 0.76,15.62 0.76,44.58 v1(1.52,45.34)
  BOTTOM w0.14: J2.54 v1(32.43,5.4)
PG_13/SH0_FLG0/SH1_FLG6/OSPI0_SEL4B: length 41.4
  TOP w0.14: U1.B1 23.42,60.14 v1(23.02,60.54)
  L8_SIG w0.127: v1(1.52,41.66) 2.12,42.25 2.12,55.52 3.72,57.12 11.15,57.12 12.59,58.56 16.78,58.56 18.76,60.54 v1(23.02,60.54)
  BOTTOM w0.14: J3.9 1.78,41.4 v1(1.52,41.66)
PG_14/TM0_TMR10/SPI0_SEL2B/SMC0_ADDR25/TM0_ACI10: length 44.1
  TOP w0.14: v1(26.62,59.74) U1.C2
  L5_SIG w0.127: v1(26.62,59.74) 25.02,59.74 24.62,60.14 17.79,60.14 17.4,59.75 16.32,59.75 15.81,60.26 14.14,60.26 11.62,57.74 4.46,57.74 2.41,55.69 2.41,41.78 v1(1.52,40.89)
  BOTTOM w0.14: J3.11 2.03,40.77 1.91,40.89 v1(1.52,40.89)
PG_15/TM0_TMR11/SPI2_RDY/SPI3_SEL5B/SMC0_ADDR24: length 74.4
  TOP w0.203: v1(26.62,58.94) U1.D3
  L4_SIG w0.127: v1(25.02,5.33) 24.38,5.97 20.76,5.97 19.37,7.37 15.88,7.37 15.37,7.87 15.37,10.29 16,10.92 16,12.51 15.21,13.3 15.21,32.49 18.78,36.06 18.78,39.93 18.66,40.06 18.66,41.03 16.89,42.8 16.89,43.24 17.53,43.88 17.53,45.21 17.26,45.48 17.26,49.25 17.64,49.63 17.64,55 18.38,55.74 18.38,56.72 18.64,56.98 18.66,56.98 v1(19.82,58.14)
  L8_SIG w0.127: v1(19.82,58.14) 20.62,58.94 v1(26.62,58.94)
  BOTTOM w0.14: J2.30 24.81,5.54 v1(25.02,5.33)
PH_00/TM0_TMR12/SPI3_SEL7B/SMC0_ADDR23/TM0_ACI12: length 70.4
  TOP w0.14: v1(39.88,5.33) 38.73,6.48 32.89,6.48 32.07,7.3 v1(32.07,7.87)
  TOP w0.203: v1(27.42,58.14) U1.E4
  L5_SIG w0.127: v1(39.88,5.33) 38.21,7 38.21,16.99 36.2,19.01 36.2,30.1 34.29,32 34.29,32.66 33.2,33.75 33.2,35.95 33.06,36.09 33.06,36.17 33.06,36.8 33.06,36.8 33.06,38.64 33.03,38.68 33.03,49.13 32.42,49.74 30.82,49.74 30.22,50.34 30.22,53.14 29.42,53.94 29.42,56.94 28.62,57.74 U1.E4 v1(27.42,58.14)
  BOTTOM w0.14: v1(32.07,7.87) 31.8,7.6 J2.52
PH_01/TM0_TMR13/SPI0_RDY/SMC0_ADDR22/TM0_ACI13: length 76.5
  TOP w0.14: v1(38.61,5.33) 38.1,5.84 26.29,5.84 v1(24,8.13)
  TOP w0.203: v1(28.22,57.34) U1.F5
  L5_SIG w0.127: v1(28.22,57.34) U1.F5 28.62,53.74 29.42,52.94 29.42,49.14 29.62,48.94 32.42,48.94 32.7,48.66 32.7,39.12 32.11,38.54 32.11,34.23 32.43,33.91 32.58,33.91 33.08,33.4 33.08,30.59 35.81,27.85 35.81,18.92 37.85,16.89 37.85,6.54 38.61,5.78 v1(38.61,5.33)
  BOTTOM w0.14: J2.26 23.54,7.67 v1(24,8.13)
PH_02/SH0_FLG1/SPI2_SELB/TM0_TMR14/SMC0_ADDR21: length 40.5
  TOP w0.203: v1(28.22,56.54) U1.G5
  L8_SIG w0.127: v1(5.33,38.35) 5.95,38.35 9.65,42.05 9.65,49.66 10.86,50.86 17.84,50.86 19.32,52.34 23.87,52.34 24.47,52.94 28.62,52.94 29.42,53.74 29.42,55.14 29.22,55.34 28.82,55.34 28.62,55.54 U1.G5 v1(28.22,56.54)
  BOTTOM w0.14: v1(5.33,38.35) 5.46,38.23 J3.20
PH_03/ETH0_MDC/TRACE0_D08/SMC0_AMS1B: length 32.3
  TOP w0.14: v1(26.62,54.14) U1.K3
  L8_SIG w0.127: v1(4.57,42.54) 5.59,42.54 7.37,44.32 7.37,45.8 8.17,46.6 8.17,50.4 9.83,52.06 17.39,52.06 19.87,54.54 26.22,54.54 v1(26.62,54.14)
  BOTTOM w0.14: J3.5 3.31,42.54 v1(4.57,42.54)
PH_04/ETH0_MDIO/TRACE0_D09/SMC0_AMS2B: length 39.6
  TOP w0.14: v1(15.62,56.04) 16.73,57.15 23.37,57.15 23.56,57.34 25.82,57.34 U1.F2
  L7_SIG w0.127: v1(15.62,56.04) 14.89,56.77 3.68,56.77 2.03,55.12 2.03,43.85 1.52,43.34 v1(1.52,43.31)
  BOTTOM w0.14: v1(1.52,43.31) 2.03,43.31 2.03,43.31 J3.3
PH_05/ETH0_RXD0/TRACE0_D10/SMC0_AMS3B: length 38.4
  TOP w0.14: v1(25.82,55.74) U1.H2
  L8_SIG w0.127: v1(25.82,55.74) 25.42,56.14 20.39,56.14 17.02,52.77 8.65,52.77 7.02,51.14 7.02,48.24 3.56,44.77 3.56,40.26 v1(1.52,38.23)
  BOTTOM w0.14: v1(1.52,38.23) 2.16,38.23 2.16,38.23 J3.19
PH_06/ETH0_RXD1/TRACE0_D11/SMC0_ABE0B: length 42.2
  TOP w0.203: v1(27.42,54.14) U1.K4
  L8_SIG w0.127: v1(27.42,54.14) 27.02,54.54 27.02,56.74 26.82,56.94 18.02,56.94 16.35,55.27 10.57,55.27 6.52,51.21 6.52,48.43 3.05,44.96 3.05,40.64 v1(1.52,39.12)
  BOTTOM w0.14: J3.17 1.78,38.86 v1(1.52,39.12)
PH_07/ETH0_RXCLK_REFLCK/TRACE0_D12/SMC0_ABE1B: length 40.4
  TOP w0.203: v1(28.22,54.14) U1.K5
  L8_SIG w0.127: v1(28.22,54.14) 27.82,53.74 19.58,53.74 17.53,51.69 9.93,51.69 8.5,50.26 8.5,46.47 7.7,45.67 7.7,41.82 5.82,39.94 4,39.94 v1(1.52,37.46)
  BOTTOM w0.14: v1(1.52,37.46) 3.05,37.46 J3.21
PH_08/ETH0_RXCTL_RXDV/TRACE0_D13/SMC0_AOEB: length 39.8
  TOP w0.14: U1.F1 23.73,56.94 23.45,56.66 23.45,55.99 23.31,55.85 19.53,55.85 18.86,55.18 17.28,55.18 v1(16.42,56.04)
  L5_SIG w0.127: v1(4.57,37.34) 3.92,37.99 3.92,44.91 6.69,47.73 6.69,52.6 9.69,55.6 15.98,55.6 v1(16.42,56.04)
  BOTTOM w0.14: J3.23 4.19,36.96 v1(4.57,37.34)
PH_09/ETH0_TXD0/TRACE0_D14/SMC0_ARDYB: length 44.6
  TOP w0.203: v1(26.62,55.74) U1.H3
  L5_SIG w0.127: v1(1.52,33.4) 2.16,34.04 4.78,34.04 5.02,34.28 5.02,34.28 5.66,34.92 5.66,34.92 6.77,36.02 6.77,42.69 8.13,44.05 8.13,50.23 10.24,52.34 16.59,52.34 18.79,54.54 21.02,54.54 22.62,56.14 26.22,56.14 v1(26.62,55.74)
  BOTTOM w0.14: v1(1.52,33.4) 1.91,33.78 J3.33
PH_10/ETH0_TXD1/TRACE0_D15/SMC0_ADDR8: length 44.6
  TOP w0.203: v1(26.62,56.54) U1.G3
  L5_SIG w0.127: v1(1.52,34.16) 1.84,34.48 4.76,34.48 4.88,34.61 4.89,34.61 5.33,35.05 5.33,35.06 6.44,36.16 6.44,42.83 7.76,44.15 7.76,50.43 10.22,52.9 16.51,52.9 18.55,54.94 19.02,54.94 20.02,55.94 21.42,55.94 22.42,56.94 24.82,56.94 25.22,56.54 v1(26.62,56.54)
  BOTTOM w0.14: J3.31 1.78,34.42 v1(1.52,34.16)
PH_11/ETH0_RXD2/SMC0_ADDR9: length 38.8
  TOP w0.203: v1(26.62,57.34) U1.F3
  L8_SIG w0.127: v1(26.62,57.34) 17.72,57.34 16.92,56.54 13.36,56.54 12.76,55.94 10.67,55.94 6.02,51.3 6.02,48.54 2.54,45.09 2.54,40.85 1.57,39.88 v1(1.52,39.88)
  BOTTOM w0.14: v1(1.52,39.88) 1.9,39.5 J3.15
PH_12/ETH0_RXD3/SMC0_ADDR10: length 35
  TOP w0.203: v1(26.62,54.94) U1.J3
  L8_SIG w0.127: v1(4.57,40.39) 4.02,40.94 4.02,44.45 7.52,47.95 7.52,50.24 9.67,52.39 17.21,52.39 19.76,54.94 23.82,54.94 24.22,55.34 26.22,55.34 v1(26.62,54.94)
  BOTTOM w0.14: v1(4.57,40.39) 4.32,40.13 J3.13
PH_13/ETH0_TXCTL_TXEN/SMC0_ADDR11: length 44.1
  TOP w0.203: v1(27.42,54.94) U1.J4
  L5_SIG w0.127: v1(27.42,54.94) 27.02,54.54 27.02,53.84 26.82,53.64 24.62,53.64 23.52,52.54 18.49,52.54 16.95,51 10.55,51 9.87,50.32 9.87,50.28 9.8,50.21 9.8,45.43 9.8,45.16 9.45,44.8 9.45,43.5 8.09,42.14 8.09,38.58 8.69,37.98 8.69,35.95 7.87,35.12 7.87,34.03 v1(5.46,31.62)
  BOTTOM w0.14: v1(5.46,31.62) 4.57,32.51 J3.37
PH_14/ETH0_TXCLK/SMC0_ADD12: length 41.8
  TOP w0.203: v1(27.42,55.74) U1.H4
  L5_SIG w0.127: v1(27.42,55.74) 27.02,55.34 24.32,55.34 23.72,54.74 22.42,54.74 21.42,53.74 18.5,53.74 16.77,52.01 10.42,52.01 8.46,50.05 8.46,43.91 7.1,42.55 7.1,35.89 5.99,34.78 5.99,34.78 5.16,33.95 5.16,33.95 4.57,33.36 v1(4.57,33.15)
  BOTTOM w0.14: v1(4.57,33.15) 3.18,33.15 J3.35
PH_15/ETH0_TXD2/SMC0_ADDR13: length 46.3
  TOP w0.203: v1(27.42,56.54) U1.G4
  L5_SIG w0.127: v1(27.42,56.54) 27.02,56.94 26.02,56.94 25.62,57.34 20.82,57.34 18.82,55.34 16.92,55.34 14.86,53.28 8.51,53.28 7.43,52.2 7.43,44.4 6.11,43.08 6.11,36.3 5,35.19 5,35.19 4.74,34.92 v1(1.52,34.92)
  BOTTOM w0.14: v1(1.52,34.92) 1.65,35.05 J3.29
PI_00/ETH0_TXD3/SMC0_A14: length 43.4
  TOP w0.203: v1(28.22,54.94) U1.J5
  L8_SIG w0.127: v1(28.22,54.94) U1.J5 28.62,53.74 28.22,53.34 19.68,53.34 17.65,51.31 10.1,51.31 8.83,50.04 8.83,46.23 8.06,45.47 8.06,41.38 6.24,39.56 4.34,39.56 2.42,37.64 2.42,36.58 v1(1.52,35.69)
  BOTTOM w0.14: v1(1.52,35.69) 2.16,35.69 2.16,35.69 J3.27
PI_01/SH1_FLG0/ETH0_PTPCLKIN0/TWI2_SCL/SMC0_ADDR15: length 45.4
  TOP w0.14: U1.D1 23.82,58.54 23.62,58.34 23.62,57.91 23.24,57.53 16.35,57.53 14.85,56.04 v1(14.22,56.04)
  L7_SIG w0.127: v1(14.22,56.04) 13.94,56.32 3.81,56.32 2.54,55.05 2.54,40.39 v1(4.57,38.35)
  BOTTOM w0.14: v1(4.57,38.35) 5.21,37.72 5.21,37.34 5.59,36.96 J3.24
PI_02/SH1_FLG1/ETH0_PTPAUXIN0/TWI3_SDA/SMC0_ADDR16: length 41.4
  TOP w0.203: v1(27.42,57.34) U1.F4
  L5_SIG w0.127: v1(27.42,57.34) 27.02,57.74 20.34,57.74 19.62,57.02 18.1,57.02 16.32,55.25 9.91,55.25 7.09,52.43 7.09,44.61 5.78,43.3 5.78,36.63 v1(5.46,36.32)
  BOTTOM w0.14: v1(5.46,36.32) J3.26
PI_03/TWI1_SCL/SH0_FLG4/ETH0_PTPPPS1/SMC0_ADDR17: length 45.5
  TOP w0.203: v1(26.62,58.14) U1.E3
  L5_SIG w0.127: v1(4.57,35.37) 2.92,37.02 2.92,45.04 6.03,48.15 6.03,53.02 9.91,56.9 16,56.9 17.65,58.54 26.22,58.54 v1(26.62,58.14)
  BOTTOM w0.14: v1(4.57,35.37) 5.08,35.05 J3.30
PI_04/TWI1_SDA/SH0_FLG5/ETH0_PTPPPS0/SMC0_ADDR18: length 43.1
  TOP w0.14: U1.D2 25.86,58.9 23.69,58.9 23.47,58.67 19.35,58.67 v1(18.82,58.14)
  L5_SIG w0.127: v1(4.57,36.32) 3.42,37.47 3.42,44.97 6.36,47.96 6.36,52.78 10.1,56.52 16.19,56.52 17.82,58.14 v1(18.82,58.14)
  BOTTOM w0.14: J3.28 5.21,35.69 v1(4.57,36.32)
PI_05/ETH0_PTPPPS2/OSPI0_SEL2B/SHO_FLG15/SMC0_ADDR19/TM0_ACLK2: length 46.8
  TOP w0.14: v2(9.62,58.42) 11.21,56.83 15.18,56.83 17.36,59.02 23.33,59.02 23.65,59.34 U1.C1
  BOTTOM w0.14: v2(9.62,58.42) 10.59,57.45 10.59,51.77 12.73,49.62 12.73,45.37 8.32,40.96 8.32,38.48 8.83,37.97 8.83,34.62 8.62,34.42 J3.32
PI_06/ETH0_PTPPPS3/SMC0_ADDR20/TM0_ACLK14: length 40.8
  TOP w0.203: v1(28.22,55.74) U1.H5
  L5_SIG w0.127: v1(28.22,55.74) 27.82,55.34 27.82,53.74 27.22,53.14 24.81,53.14 23.88,52.21 20.1,52.21 19.84,51.94 18.58,51.94 17.3,50.67 10.73,50.67 10.13,50.08 10.13,45.57 10.13,45.02 9.78,44.66 9.78,43.37 9.19,42.78 9.19,40.57 9.42,40.34 9.42,39.28 9.08,38.94 9.08,35.87 8.26,35.04 v1(8.26,33.65)
  BOTTOM w0.14: J3.34 8.13,33.78 v1(8.26,33.65)
SPI2D2_D3_EN*: length 29.9
  TOP w0.14: v2(10.79,60.71) 11.83,60.71 11.93,60.61 U24.19 ; U5.1 v2(13.2,43.05) 12.85,43.4 9.17,43.4 8.88,43.11 U10.1
  BOTTOM w0.14: R53.2 R54.1 v2(13.2,43.05) 13.2,49.85 11.07,51.99 11.07,58.09 10.79,58.36 v2(10.79,60.71)
SPI2IFLASH_CS_EN*: length 46.5
  TOP w0.14: U24.18 10.31,61.36 v2(9.65,60.71) ; U9.1 v2(17.52,42.98)
  L4_SIG w0.127: v2(9.65,60.71) 11.13,59.23 11.13,51.68 12.75,50.05 12.75,44.88 11.28,43.41 10.33,43.41 8.32,41.4 8.32,38.86 v1(10.86,36.32)
  L7_SIG w0.127: v2(17.52,42.98) 16.89,42.35 16.51,42.35 15.44,41.29 15.44,39.3 12.47,36.32 v1(10.86,36.32)
  BOTTOM w0.14: R55.2 17.21,42.67 v2(17.52,42.98) 18.15,42.98 18.29,42.84 R56.1
SPIFLASH_CS*: length 7.4
  TOP w0.14: U9.4 20.13,40.32 20.57,39.88 20.57,37.15 20.38,36.96 U4.7 v2(17.78,36.96)
  BOTTOM w0.14: v2(17.78,36.96) R46.2
SPIFLASH_SPI2D2: length 5.4
  TOP w0.14: U4.9 v2(10.92,38.23) 11.68,38.99 11.68,40.13 11.5,40.32 U10.4
  BOTTOM w0.14: v2(10.92,38.23) 9.85,38.23 R48.2
SPIFLASH_SPI2D3: length 21.7
  TOP w0.14: U4.1 v2(17.78,29.34) 13.12,29.34 11.14,31.32 11.14,32.12 11.28,32.26 12.7,32.26 12.95,32.51 12.95,33.22 12.52,33.65 12.52,36.4 15.18,39.05 15.18,39.23 15.5,39.55 U5.4
  BOTTOM w0.14: R47.2 v2(17.78,29.34)
STUSB_ALERT: length 7.6
  TOP w0.14: U6.19 49.69,95.47 50.16,95 R112.1
STUSB_RESETB: length 4.2
  TOP w0.254: U6.6 43.71,92.22 43.05,91.57 R111.2
  TOP w0.305: R127.1 R111.2
SYS_BMODE0: length 44.5
  TOP w0.14: 8.26,79.02 v2(8.26,80.9)
  TOP w0.203: v1(25.02,52.54) U1.L1
  BOTTOM w0.14: v2(8.26,80.9) 8.26,79.83 R24.1 8.39,74.6 11.14,71.86 11.14,65.36 13.16,63.33 13.16,53.41 14.29,52.28 20.8,52.28 20.91,52.17 22.73,52.17 22.88,52.32 23.9,52.32 24.12,52.54 v1(25.02,52.54)
SYS_BMODE1: length 37.1
  TOP w0.14: v2(3.17,68.96) S1.2 ; U1.G2 25.82,56.54 v1(24.22,56.54)
  L8_SIG w0.127: v2(3.17,68.96) 3.75,68.39 5.48,68.39 5.49,68.37 5.94,68.37 5.95,68.39 15.3,68.39 15.88,68.96 v2(17.4,68.96)
  BOTTOM w0.14: v2(3.17,68.96) 3.05,69.09 3.05,69.85 R25.1 ; v2(17.4,68.96) 18.48,67.88 18.48,60.9 19.32,60.05 19.32,57.85 19.93,57.24 23.42,57.24 v1(24.22,56.54)
SYS_BMODE2: length 48.8
  TOP w0.14: U1.N1 24.12,51.34 v1(23.72,51.74) ; 3.17,79.02 v2(3.17,80.9)
  BOTTOM w0.14: v1(23.72,51.74) 22.94,50.96 20.91,50.96 20.76,51.12 20.44,51.12 19.62,51.94 14.1,51.94 12.82,53.22 12.82,63.19 10.79,65.21 10.79,71.69 8,74.49 8,77.22 5.59,79.63 3.42,79.63 R26.1 3.17,79.88 v2(3.17,80.9)
SYS_CLKIN0: length 50.8
  TOP w0.14: R27.2 19.75,53.54 23.62,53.54 v1(25.02,54.94) U1.J1 ; R34.2 v1(49.34,29.21)
  L4_SIG w0.127: v1(25.02,54.94) U1.J1 26.02,54.54 26.22,54.34 26.22,53.74 26.62,53.34 29.84,53.34 30.23,52.96 30.23,50.54 31.03,49.74 36.37,49.74 36.61,49.5 36.61,48.24 36.7,48.14 39.62,48.14 39.82,47.94 39.82,45.27 41.47,43.62 41.47,42.62 43.62,40.45 43.62,38.86 44.97,37.52 44.97,32.88 48.64,29.21 v1(49.34,29.21)
SYS_CLKIN1: length 67.3
  TOP w0.14: R40.2 v1(50.41,29.21) ; v1(18.02,47.74) 17.82,47.54 R28.2
  TOP w0.203: v1(25.02,58.14) 25.82,58.14 U1.E2
  L4_SIG w0.127: 25.25,57.91 25.25,57.91 v1(25.02,58.14) ; 25.25,57.91 26.22,56.94 26.82,56.94 27.02,56.74 27.02,53.94 27.22,53.74 31.22,53.74 31.82,53.14 31.82,51.14 32.42,50.54 37.97,50.54 38.23,50.28 38.23,49.13 38.42,48.94 40.42,48.94 40.62,48.74 40.62,44.96 42.56,43.02 42.56,42.6 44.7,40.45 44.7,38.42 45.27,37.85 45.27,33.09 48.7,29.65 49.53,29.65 49.97,29.21 v1(50.41,29.21) ; 25.25,57.91 v1(25.02,58.14) ; v1(25.02,58.14) 23.62,56.74 23.62,55.14 23.22,54.74 20.52,54.74 20.12,54.34 20.12,47.54 19.72,47.14 18.62,47.14 v1(18.02,47.74)
SYS_CLKOUT: length 39.9
  TOP w0.14: v1(25.82,54.94) U1.J2
  L5_SIG w0.127: v1(25.82,54.94) 25.42,54.54 24.42,54.54 23.22,53.34 18.74,53.34 16.83,51.44 10.41,51.44 9.47,50.49 9.47,46.85 9.47,45.29 9.12,44.94 9.12,43.64 7.76,42.28 7.76,35.61 7.54,35.39 7.54,34.46 v1(5.46,32.38)
  BOTTOM w0.14: v1(5.46,32.38) 6.65,32.38 J3.38
SYS_FAULT: length 16.6
  TOP w0.14: R113.1 43.23,47.43 42.71,47.43 v1(42.22,46.94)
  TOP w0.203: U1.D18 v1(39.42,58.94)
  BOTTOM w0.14: v1(39.42,58.94) 39.82,58.54 41.42,58.54 41.78,58.18 41.78,47.38 v1(42.22,46.94)
SYS_FAULT*: length 106.4
  TOP w0.14: R59.2 R60.2 v1(23.02,66.34)
  TOP w0.203: v1(37.82,56.54) U1.G16
  L4_SIG w0.127: v1(20.38,9.33) 20.38,10.48 21.65,11.75 21.65,17.14 20.89,17.91 20.89,26.1 18.48,28.51 18.48,35.28 19.11,35.92 19.11,40.07 18.99,40.2 18.99,41.4 18.16,42.23 18.16,45.15 17.59,45.72 17.59,49.11 17.97,49.49 17.97,54.86 21.91,58.8 21.91,64.14 22.42,64.64 22.42,65.74 v1(23.02,66.34)
  L5_SIG w0.127: v1(37.82,56.54) 37.42,56.94 31.72,56.94 31.02,57.64 31.02,60.24 30.22,61.04 30.22,62.04 29.62,62.64 24.52,62.64 23.72,63.44 23.72,65.64 v1(23.02,66.34)
  L8_SIG w0.127: v1(9.4,16.51) 11.81,16.51 13.34,14.99 13.34,11.94 13.97,11.3 19.94,11.3 20.38,10.86 v1(20.38,9.33)
  BOTTOM w0.14: J3.88 9.27,16.64 v1(9.4,16.51)
SYS_HWRST*: length 156.4
  TOP w0.14: v1(48.96,34.35) 48.96,34.63 U19.K5 ; U4.3 17.53,31.88 16.83,32.58 13.61,32.58 12.66,31.62 v2(12.64,31.62) ; U24.12 13.61,65.01 13.47,65.15 v2(12.76,65.15) ; v1(50.67,31.31) 50.67,29.98 51.16,29.5 52.1,29.5 53.15,28.45 55.56,28.45 56.45,27.56 56.45,23.94 56.59,23.8 U14.2 57.42,22.33 R75.2 R73.2 ; v1(23.02,63.14) R57.1
  TOP w0.203: U1.D6 v1(29.02,58.94)
  L4_SIG w0.127: v1(9.4,14.22) 13.46,18.29 13.46,21.84 12.76,22.54 12.76,24.57 13.59,25.4 13.59,25.91 12.83,26.67 12.83,29.91 12.64,30.1 v2(12.64,31.62) 12.01,32.25 11.06,32.25 10.54,32.77 10.54,35.31 11.81,36.58 11.81,37.4 11.52,37.69 10.12,37.69 9.42,38.4 9.42,41.48 9.78,41.85 10.93,41.85 11.72,42.63 11.72,43.04 13.08,44.41 13.08,50.74 11.62,52.2 11.62,57.59 12.76,58.74 v2(12.76,65.15)
  L8_SIG w0.127: v2(12.76,65.15) 17.46,65.15 18.16,65.85 20.31,65.85 v1(23.02,63.14) 23.52,62.64 27.72,62.64 28.62,61.74 28.62,59.34 v1(29.02,58.94) ; v2(12.64,31.62) 13.2,31.06 14.43,31.06 15.54,32.18 17.6,32.18 19.75,30.04 19.75,29.34 21.59,27.5 27.94,27.5 29.02,28.57 33.17,28.57 33.43,28.83 35.84,28.83 36.73,29.72 37.53,29.72 38.04,30.23 42.16,30.23 43.24,31.31 44.64,31.31 46.36,33.02 47.62,33.02 v1(48.96,34.35) 50.67,32.64 v1(50.67,31.31)
  BOTTOM w0.14: v1(9.4,14.22) 8.89,14.73 8.26,14.73 8,14.73 J3.94
SYS_RESOUT*: length 13.2
  TOP w0.14: R61.2 v1(23.02,64.54)
  TOP w0.203: v1(29.82,58.14) U1.E7
  L8_SIG w0.127: v1(23.02,64.54) 27.69,64.54 28.46,63.76 28.46,62.5 29.42,61.54 29.42,58.54 v1(29.82,58.14)
SYS_XTAL0: length 6.6
  TOP w0.14: U1.R1 18.92,49.74 R18.1
SYS_XTAL1: length 16
  TOP w0.14: v1(19.62,47.74) 19.32,47.44 R19.1 ; v1(24.22,58.14) 24.62,57.74 U1.E1
  L4_SIG w0.127: v1(19.62,47.74) 19.11,48.25 19.11,54.63 20.42,55.94 21.22,55.94 22.62,57.34 23.42,57.34 v1(24.22,58.14)
TARGET_RESET*: length 92.1
  TOP w0.14: U11.1 56.13,39.68 55.82,39.37 v1(54.61,39.37) 53.86,39.37 53.09,38.6 53.09,34.23 50.61,31.75 50.37,31.75 50.18,31.56 v1(50.18,29.91) ; R85.2 v2(10.79,48.9)
  L4_SIG w0.127: 11.11,43.75 10.16,43.75 7.56,41.15 7.56,26.86 v1(8.26,26.16) ; 12.3,44.94 12.3,47.39 v2(10.79,48.89)
  L4_SIG w0.14: 11.11,43.75 12.3,44.94
  L8_SIG w0.127: v1(8.26,26.16) 8.61,25.81 13.18,25.81 14.54,24.45 22.29,24.45 23.62,23.11 27.73,23.11 28.6,22.25 33.94,22.25 35.5,23.81 35.5,25.8 36.05,26.35 36.12,26.35 37.51,26.35 38.28,27.12 38.28,27.69 38.89,28.3 46.46,28.3 48.07,29.91 v1(50.18,29.91)
  BOTTOM w0.14: R63.2 v1(54.61,39.37) ; J3.58 v1(8.25,26.16)
TWI2_SCL: length 188.5
  TOP w0.14: R15.2 v1(37.66,40.13) ; U24.9 15.11,65.53 15.18,65.6 v2(15.18,66.67) ; v1(27.81,1.65) 29.38,3.21 48.51,3.21 49.02,3.73 v1(49.02,4.44) ; U3.12 v1(52.1,22.07)
  TOP w0.254: v2(44.51,90.36) 45.11,90.95 U6.7
  L4_SIG w0.127: v1(16.13,36.32) 16.13,36.83 16.8,37.5 18,37.5 18.41,37.91 18.41,39.83 18.26,39.99 18.26,40.92 16.38,42.8 16.38,45.21 16.89,45.72 16.89,49.35 17.27,49.73 17.27,57.72 19.43,59.88 19.43,59.9 19.56,60.02 19.56,62.29 v2(15.18,66.67) 15.18,67.75 21.34,73.91 21.34,84.96 22.61,86.23 37.02,86.23 41.15,90.36 v2(44.51,90.36)
  L7_SIG w0.127: v1(49.02,4.44) 49.02,11.75 52.1,14.83 v1(52.1,22.07)
  L8_SIG w0.127: v1(16.13,36.32) 16.13,36.83 16.89,37.59 20.07,37.59 24.22,41.74 29.18,41.74 30.59,40.34 30.79,40.34 31.01,40.12 34.68,40.12 35.05,39.75 35.89,39.75 36.07,39.57 37.1,39.57 v1(37.66,40.13) 38.23,39.56 38.73,39.56 39.31,38.99 49.97,38.99 52.91,36.05 52.91,30.43 51.31,28.83 51.31,28 51.74,27.57 51.74,26.32 51.67,26.25 51.67,22.5 v1(52.1,22.07)
  BOTTOM w0.14: v1(27.81,1.65) 27.99,1.83 J2.39 ; R15.2 v1(37.66,40.13)
TWI2_SDA: length 187.9
  TOP w0.14: U24.10 14.61,64.62 v2(14.61,65.98) ; v1(49.02,2.16) 48.31,2.87 29.92,2.87 v1(28.7,1.65) ; U3.19 v1(52.1,26.07) ; R14.2 v1(38.73,40.13)
  TOP w0.254: U6.8 v2(45.6,89.92)
  L4_SIG w0.127: v2(45.6,89.92) 45.6,90.68 45.29,91 41.28,91 36.89,86.61 22.16,86.61 20.83,85.28 20.83,74.29 14.8,68.26 14.8,67.22 14.61,67.04 14.61,65.98 ; 14.61,65.98 v2(14.61,65.98) ; 14.61,65.98 19.28,61.31 19.28,60.2 16.89,57.81 16.89,55.82 15.99,54.91 15.99,44.18 14.61,42.8 14.61,40.58 v1(15.88,39.31)
  L7_SIG w0.127: v1(52.1,26.07) 53.4,24.76 53.4,20.7 52.64,19.94 52.64,14.54 49.53,11.43 49.53,2.67 v1(49.02,2.16)
  L8_SIG w0.127: v1(52.1,26.07) 52.1,27.73 51.64,28.2 51.64,28.65 53.33,30.34 53.33,36.19 50.19,39.32 39.55,39.32 v1(38.73,40.13) 38.24,40.63 34.91,40.63 34.73,40.45 32.07,40.45 30.44,42.08 23.09,42.08 19.81,38.8 16.38,38.8 v1(15.88,39.31)
  BOTTOM w0.14: R14.2 v1(38.73,40.13) ; v1(28.7,1.65) 28.62,1.73 J2.41
UART0_EN*: length 32
  TOP w0.14: v2(11.43,59.69) 13.91,59.69 14.11,59.89 U24.20 ; U7.13 19.3,78.39 19.56,78.13 19.56,76.69 19.3,76.44 U7.10 16.14,76.44 v2(16,76.58)
  L4_SIG w0.127: v2(16,76.58) 16,75.06 15.37,74.42 15.37,72.01 10.16,66.8 10.16,63.56 11.43,62.29 v2(11.43,59.69)
  BOTTOM w0.14: R81.2 R82.1 v2(16,76.58)
UART0_FLOW_EN*: length 35.4
  TOP w0.14: U7.4 13.59,77.09 13.62,77.12 13.87,77.12 v2(14.73,77.98) 13.67,79.04 U7.1 ; U24.21 14.53,60.53 14.53,59.42 13.91,58.8 10.58,58.8 v2(9.65,59.69)
  L4_SIG w0.127: v2(9.65,59.69) 9.02,60.32 9.02,63.88 9.53,64.39 9.53,68.71 14.1,73.28 14.1,74.68 15.37,75.95 15.37,77.34 v2(14.73,77.98)
  BOTTOM w0.14: R83.2 R84.1 v2(14.73,77.98)
UNNAMED_2_ADSPSC59X_I55_DMC0VREF0: length 13.4
  TOP w0.203: v1(33.82,60.54) U1.A11
  L7_SIG w0.127: v1(43.02,56.54) 42.32,57.24 42.32,59.44 41.62,60.14 34.22,60.14 v1(33.82,60.54)
  BOTTOM w0.14: R2.2 v1(43.02,56.54)
UNNAMED_2_CAP_I43_N1: length 7.8
  TOP w0.203: U8.H1 32.22,72.74 ; U8.M8 35.79,78.77 v1(35.42,79.14)
  TOP w0.406: 36.22,81.74 v1(36.22,80.74) ; 32.22,72.74 C39.2
  L4_SIG w0.406: v1(36.22,80.74) 34.82,80.74 34.62,80.54 34.62,79.34 34.82,79.14 v1(35.42,79.14)
UNNAMED_2_CAP_I107_N1: length 5.5
  TOP w0.254: U2.1 C27.1 51.95,69.78 51.51,70.22 R7.1 C36.1
UNNAMED_2_ICIS4XTR16256_I54_ZQ: length 3.3
  TOP w0.203: U8.L8 34.62,79.14 R4.1
UNNAMED_4_CAP_I12_N2: length 1.2
  BOTTOM w0.305: R17.1 C47.2
UNNAMED_4_CAP_I23_N1: length 14.5
  TOP w0.203: v1(42.32,50.14) 41.84,49.66 40.89,49.66 U1.R20
  TOP w0.508: v1(45.97,53.3) C44.1 47.07,53.22 C45.1 50.57,53.22 50.94,52.84 FL1.3
  L8_SIG w0.508: v1(45.97,53.3) 43.38,53.3 42.32,52.21 v1(42.32,50.14)
UNNAMED_4_FLTR3P_I22_IN: length 3.5
  TOP w0.508: FL1.1 57.64,52.84 58,53.21 R16.2
